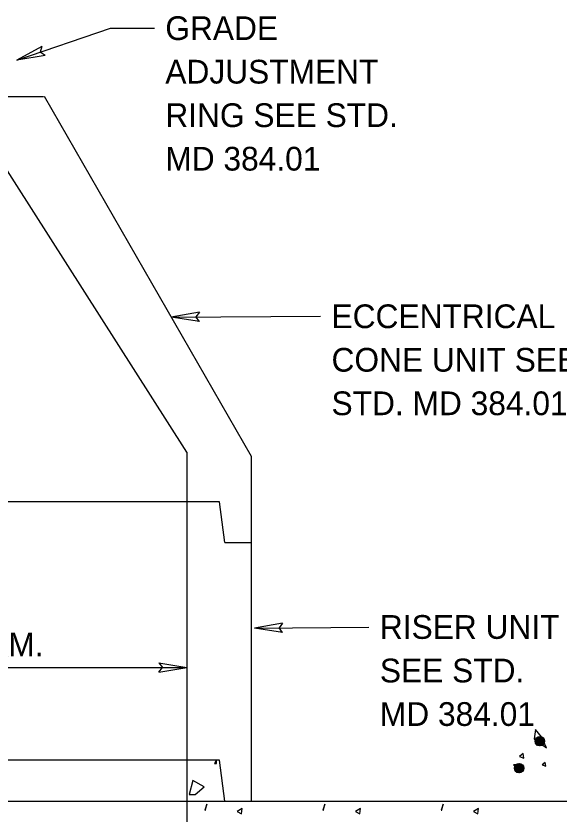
# Model space of a CAD drawing. Extents: x 8.6 to 15.9, y 6.4 to 16.6.
# Drawn here: x 10.539 to 11.914, y 12.809 to 14.827 of the extents above; entities that cross this region are included whole.
import ezdxf

# ---------------------------------------------------------------- set-up
doc = ezdxf.new("R2010")
doc.units = 0
for name, color, linetype in [('DETL-DIMS', 7, 'Continuous'), ('DETL-LINE', 7, 'Continuous'), ('DETL-NOTE', 7, 'Continuous'), ('DETL-PATT', 7, 'Continuous')]:
    doc.layers.add(name, color=color, linetype=linetype)

msp = doc.modelspace()

# ---------------------------------------------------------------- linework, layer by layer
at = {"layer": 'DETL-DIMS'}
for p, q in [((10.5416, 14.7154), (10.7783, 14.7962)), ((10.7783, 14.7962), (10.8894, 14.7962)), ((10.605, 14.7495), (10.5416, 14.7154)), ((10.605, 14.7495), (10.6005, 14.7355)), ((10.6127, 14.7271), (10.6005, 14.7355)), ((10.6127, 14.7271), (10.5416, 14.7154)), ((11.0033, 14.078), (10.9322, 14.0658)), ((10.9322, 14.0658), (11.31, 14.0678)), ((11.0034, 14.0543), (10.9322, 14.0658)), ((11.0033, 14.078), (10.9945, 14.0661)), ((11.0034, 14.0543), (10.9945, 14.0661)), ((11.2139, 13.292), (11.1429, 13.2795)), ((11.1429, 13.2795), (11.4325, 13.2822)), ((11.2141, 13.2683), (11.1429, 13.2795)), ((11.2139, 13.292), (11.2051, 13.2801)), ((11.2141, 13.2683), (11.2051, 13.2801)), ((9.6604, 13.1802), (10.972, 13.1802)), ((10.9008, 13.1918), (10.972, 13.1802)), ((10.9008, 13.1918), (10.9098, 13.18)), ((10.9009, 13.1681), (10.972, 13.1802)), ((10.9009, 13.1681), (10.9098, 13.18))]:
    msp.add_line(p, q, dxfattribs=at)
at = {"layer": 'DETL-LINE'}
for p, q in [((9.511, 14.6237), (10.609, 14.6237)), ((10.972, 13.7241), (10.3968, 14.6237)), ((10.6104, 14.6245), (11.1346, 13.7139)), ((10.972, 13.7241), (10.972, 12.6091)), ((11.1346, 13.7139), (11.1346, 12.842)), ((11.0541, 13.5991), (9.5929, 13.5991)), ((11.0675, 13.4955), (11.0541, 13.5991)), ((11.0675, 13.4955), (11.1346, 13.4955)), ((11.8622, 12.9857), (11.8534, 12.9945)), ((11.8624, 12.9861), (11.8537, 12.995)), ((11.8637, 12.998), (11.8548, 12.9893)), ((11.8638, 13.0035), (11.8549, 12.9948)), ((11.8561, 12.9859), (11.8562, 12.9984)), ((11.8649, 12.9884), (11.8562, 12.9973)), ((11.8652, 12.9888), (11.8565, 12.9977)), ((11.8665, 12.9953), (11.8575, 12.9865)), ((11.8665, 13.0007), (11.8576, 12.992)), ((11.8589, 12.9898), (11.859, 13.0023)), ((11.8677, 12.9911), (11.8589, 13)), ((11.8589, 12.9859), (11.859, 12.9984)), ((11.8676, 12.9856), (11.8589, 12.9945)), ((11.868, 12.9915), (11.8592, 13.0004)), ((11.8679, 12.986), (11.8592, 12.9949)), ((11.86, 12.9898), (11.8601, 13.0023)), ((11.86, 12.9859), (11.8601, 12.9984)), ((11.8693, 13.0035), (11.8603, 12.9947)), ((11.8692, 12.998), (11.8603, 12.9892)), ((11.8705, 12.9938), (11.8617, 13.0027)), ((11.8704, 12.9883), (11.8617, 12.9973)), ((11.8707, 12.9887), (11.8619, 12.9976)), ((11.8708, 12.9943), (11.862, 13.0031)), ((11.8627, 12.982), (11.8628, 12.9944)), ((11.8628, 12.9897), (11.8629, 13.0022)), ((11.8628, 12.9858), (11.8629, 12.9983)), ((11.8719, 12.9952), (11.863, 12.9864)), ((11.872, 13.0007), (11.8631, 12.992)), ((11.8638, 12.982), (11.8639, 12.9944)), ((11.8639, 12.9897), (11.864, 13.0022)), ((11.8639, 12.9858), (11.864, 12.9983)), ((11.8732, 12.9856), (11.8644, 12.9945)), ((11.8732, 12.991), (11.8645, 12.9999)), ((11.8735, 12.9915), (11.8647, 13.0004)), ((11.8735, 12.986), (11.8647, 12.9948)), ((11.8747, 12.9979), (11.8658, 12.9892)), ((11.8666, 12.9858), (11.8668, 12.9983)), ((11.8666, 12.9819), (11.8667, 12.9944)), ((11.8667, 12.9897), (11.8668, 13.0022)), ((11.876, 12.9938), (11.8672, 13.0027)), ((11.8762, 12.9942), (11.8675, 13.0031)), ((11.8677, 12.9819), (11.8678, 12.9944)), ((11.8678, 12.9897), (11.8679, 13.0022)), ((11.8678, 12.9858), (11.8679, 12.9983)), ((11.8705, 12.9858), (11.8706, 12.9983)), ((11.8706, 12.9897), (11.8707, 13.0021)), ((11.8716, 12.9897), (11.8718, 13.0021)), ((11.8716, 12.9858), (11.8718, 12.9983)), ((11.8649, 12.9829), (11.8561, 12.9918)), ((11.8652, 12.9833), (11.8564, 12.9922)), ((11.8692, 12.9925), (11.8603, 12.9837)), ((11.8704, 12.9828), (11.8616, 12.9917)), ((11.8707, 12.9832), (11.8619, 12.9921)), ((11.8747, 12.9924), (11.8658, 12.9837)), ((11.0541, 12.9456), (9.5929, 12.9456)), ((11.0675, 12.842), (11.0541, 12.9456)), ((11.8111, 12.9357), (11.8022, 12.927)), ((11.8062, 12.922), (11.8063, 12.9345)), ((11.8073, 12.922), (11.8075, 12.9345)), ((11.8166, 12.9357), (11.8077, 12.927)), ((11.8178, 12.926), (11.809, 12.9349)), ((11.8181, 12.9265), (11.8093, 12.9354)), ((11.8101, 12.922), (11.8102, 12.9344)), ((11.8112, 12.922), (11.8113, 12.9344)), ((11.814, 12.9219), (11.8141, 12.9344)), ((11.8233, 12.926), (11.8146, 12.9349)), ((11.8236, 12.9264), (11.8148, 12.9353)), ((11.8151, 12.9219), (11.8152, 12.9344)), ((11.8179, 12.9219), (11.818, 12.9344)), ((11.819, 12.9219), (11.8191, 12.9344)), ((11.8095, 12.9179), (11.8007, 12.9268)), ((11.8098, 12.9183), (11.801, 12.9272)), ((11.811, 12.9302), (11.8022, 12.9215)), ((11.8034, 12.9181), (11.8035, 12.9306)), ((11.8122, 12.9206), (11.8035, 12.9295)), ((11.8122, 12.9151), (11.8035, 12.924)), ((11.8125, 12.921), (11.8038, 12.9299)), ((11.8125, 12.9155), (11.8038, 12.9244)), ((11.8138, 12.933), (11.8049, 12.9242)), ((11.8138, 12.9275), (11.8049, 12.9187)), ((11.8062, 12.9181), (11.8063, 12.9306)), ((11.815, 12.9178), (11.8062, 12.9267)), ((11.815, 12.9233), (11.8063, 12.9322)), ((11.8153, 12.9182), (11.8065, 12.9271)), ((11.8153, 12.9237), (11.8066, 12.9326)), ((11.8073, 12.9181), (11.8074, 12.9306)), ((11.8166, 12.9302), (11.8076, 12.9214)), ((11.8165, 12.9247), (11.8076, 12.9159)), ((11.8178, 12.9205), (11.809, 12.9295)), ((11.8177, 12.9151), (11.809, 12.924)), ((11.818, 12.9154), (11.8092, 12.9244)), ((11.818, 12.921), (11.8093, 12.9298)), ((11.81, 12.9142), (11.8102, 12.9267)), ((11.8101, 12.9181), (11.8102, 12.9305)), ((11.8193, 12.9329), (11.8104, 12.9242)), ((11.8193, 12.9274), (11.8104, 12.9187)), ((11.8112, 12.9181), (11.8113, 12.9305)), ((11.8112, 12.9142), (11.8113, 12.9267)), ((11.8205, 12.9233), (11.8118, 12.9321)), ((11.8205, 12.9178), (11.8118, 12.9267)), ((11.8208, 12.9237), (11.812, 12.9326)), ((11.8208, 12.9182), (11.812, 12.9271)), ((11.822, 12.9247), (11.8131, 12.9159)), ((11.822, 12.9301), (11.8132, 12.9214)), ((11.8139, 12.9141), (11.814, 12.9266)), ((11.814, 12.918), (11.8141, 12.9305)), ((11.815, 12.9141), (11.8152, 12.9266)), ((11.8151, 12.918), (11.8152, 12.9305)), ((11.8179, 12.918), (11.818, 12.9305)), ((11.819, 12.918), (11.8191, 12.9305)), ((9.5795, 12.842), (11.0675, 12.842)), ((11.0675, 12.842), (11.957, 12.842))]:
    msp.add_line(p, q, dxfattribs=at)
for points in [[(11.861, 13.0008), (11.8533, 12.9932)], [(11.8582, 12.998), (11.8533, 12.9932)], [(11.8555, 12.9954), (11.8533, 12.9932)], [(11.8594, 12.9884), (11.8534, 12.9945)], [(11.8567, 12.9912), (11.8534, 12.9945)], [(11.854, 12.994), (11.8534, 12.9945)], [(11.8597, 12.9888), (11.8535, 12.9952)], [(11.857, 12.9916), (11.8535, 12.9952)], [(11.8543, 12.9944), (11.8535, 12.9952)], [(11.8609, 12.9953), (11.8542, 12.9887)], [(11.8622, 12.9911), (11.8547, 12.9988)], [(11.8595, 12.9939), (11.8547, 12.9988)], [(11.8568, 12.9967), (11.8547, 12.9988)], [(11.8625, 12.9915), (11.8549, 12.9993)], [(11.8598, 12.9943), (11.8549, 12.9993)], [(11.857, 12.9971), (11.8549, 12.9993)], [(11.855, 12.9898), (11.8551, 12.9995)], [(11.855, 12.9937), (11.8551, 12.9995)], [(11.855, 12.9873), (11.8551, 12.9984)], [(11.855, 12.9873), (11.855, 12.9945)], [(11.8551, 12.9976), (11.8551, 12.9995)], [(11.8561, 12.9898), (11.8562, 13.001)], [(11.8561, 12.9857), (11.8562, 12.9945)], [(11.8562, 12.9937), (11.8562, 13.001)], [(11.8562, 12.9976), (11.8562, 13.001)], [(11.865, 12.9939), (11.857, 13.0019)], [(11.8623, 12.9967), (11.857, 13.0019)], [(11.8595, 12.9994), (11.857, 13.0019)], [(11.8652, 12.9943), (11.8575, 13.0022)], [(11.8625, 12.9971), (11.8575, 13.0022)], [(11.8598, 12.9998), (11.8575, 13.0022)], [(11.8653, 13.005), (11.8576, 12.9975)], [(11.8588, 12.9833), (11.8589, 12.9945)], [(11.8589, 12.9937), (11.859, 13.0034)], [(11.859, 12.9975), (11.859, 13.0034)], [(11.859, 13.0014), (11.859, 13.0034)], [(11.8599, 12.9827), (11.86, 12.9945)], [(11.86, 12.9937), (11.8601, 13.004)], [(11.86, 12.9975), (11.8601, 13.004)], [(11.8601, 13.0014), (11.8601, 13.004)], [(11.8653, 13.005), (11.8604, 13.0002)], [(11.8678, 12.9966), (11.8604, 13.0041)], [(11.865, 12.9994), (11.8604, 13.0041)], [(11.8623, 13.0021), (11.8604, 13.0041)], [(11.868, 12.997), (11.8609, 13.0043)], [(11.8653, 12.9998), (11.8609, 13.0043)], [(11.8626, 13.0025), (11.8609, 13.0043)], [(11.8628, 12.9936), (11.8629, 13.0048)], [(11.8629, 12.9975), (11.8629, 13.0048)], [(11.8629, 13.0014), (11.8629, 13.0048)], [(11.8698, 13.004), (11.8631, 12.9974)], [(11.8639, 12.9936), (11.864, 13.005)], [(11.8639, 12.9975), (11.864, 13.005)], [(11.864, 13.0014), (11.864, 13.005)], [(11.8732, 12.9965), (11.8649, 13.005)], [(11.8705, 12.9993), (11.8649, 13.005)], [(11.8678, 13.0021), (11.8649, 13.005)], [(11.865, 13.0049), (11.8649, 13.005)], [(11.8735, 12.997), (11.8656, 13.005)], [(11.8708, 12.9997), (11.8656, 13.005)], [(11.8681, 13.0025), (11.8656, 13.005)], [(11.8731, 13.0018), (11.8659, 12.9947)], [(11.8667, 12.9936), (11.8668, 13.0049)], [(11.8668, 12.9975), (11.8668, 13.0049)], [(11.8668, 13.0014), (11.8668, 13.0049)], [(11.8758, 12.9884), (11.8672, 12.9972)], [(11.876, 12.989), (11.8675, 12.9976)], [(11.8678, 12.9936), (11.8679, 13.0047)], [(11.8678, 12.9975), (11.8679, 13.0047)], [(11.8679, 13.0014), (11.8679, 13.0047)], [(11.8755, 12.9987), (11.8686, 12.9919)], [(11.8767, 12.9944), (11.8686, 12.9864)], [(11.8768, 12.993), (11.8699, 12.9999)], [(11.8758, 12.9884), (11.8699, 12.9944)], [(11.8768, 12.9936), (11.8702, 13.0003)], [(11.876, 12.989), (11.8702, 12.9948)], [(11.8705, 12.9829), (11.8706, 12.9944)], [(11.8706, 12.9935), (11.8707, 13.0036)], [(11.8706, 12.9974), (11.8707, 13.0036)], [(11.8706, 13.0013), (11.8707, 13.0036)], [(11.8767, 12.9944), (11.8713, 12.9891)], [(11.8716, 12.9835), (11.8717, 12.9944)], [(11.8717, 12.9935), (11.8718, 13.0029)], [(11.8717, 12.9974), (11.8718, 13.0029)], [(11.8718, 13.0013), (11.8718, 13.0029)], [(11.8768, 12.993), (11.8727, 12.9971)], [(11.8768, 12.9936), (11.873, 12.9975)], [(11.8744, 12.9862), (11.8745, 12.9982)], [(11.8744, 12.9862), (11.8745, 12.9943)], [(11.8745, 12.9897), (11.8745, 13.0002)], [(11.8745, 12.9935), (11.8745, 13.0002)], [(11.8745, 12.9974), (11.8745, 13.0002)], [(11.8755, 12.9896), (11.8756, 12.9984)], [(11.8755, 12.988), (11.8756, 12.9982)], [(11.8755, 12.988), (11.8756, 12.9943)], [(11.8756, 12.9935), (11.8756, 12.9984)], [(11.8756, 12.9974), (11.8756, 12.9984)], [(11.8605, 12.9824), (11.8541, 12.989)], [(11.8596, 12.9833), (11.8541, 12.989)], [(11.8569, 12.9861), (11.8541, 12.989)], [(11.8542, 12.9889), (11.8541, 12.989)], [(11.8582, 12.9926), (11.8542, 12.9887)], [(11.8554, 12.9898), (11.8542, 12.9887)], [(11.8593, 12.983), (11.8547, 12.9877)], [(11.8593, 12.983), (11.8547, 12.9877)], [(11.8566, 12.9857), (11.8547, 12.9877)], [(11.855, 12.9873), (11.855, 12.9906)], [(11.8561, 12.9857), (11.8561, 12.9906)], [(11.8593, 12.983), (11.8561, 12.9863)], [(11.8637, 12.9925), (11.8564, 12.9854)], [(11.8609, 12.9898), (11.8564, 12.9854)], [(11.8581, 12.9871), (11.8564, 12.9854)], [(11.8605, 12.9824), (11.8564, 12.9867)], [(11.8588, 12.9833), (11.8589, 12.9906)], [(11.8593, 12.983), (11.8588, 12.9835)], [(11.8662, 12.9816), (11.8589, 12.989)], [(11.8605, 12.9824), (11.8591, 12.9839)], [(11.8667, 12.9817), (11.8592, 12.9894)], [(11.8664, 12.9897), (11.8595, 12.9829)], [(11.8636, 12.987), (11.8595, 12.9829)], [(11.8609, 12.9843), (11.8595, 12.9829)], [(11.8599, 12.9827), (11.86, 12.9906)], [(11.8662, 12.9816), (11.8616, 12.9862)], [(11.8667, 12.9817), (11.8619, 12.9867)], [(11.8627, 12.9818), (11.8628, 12.9905)], [(11.8719, 12.9897), (11.8637, 12.9816)], [(11.8691, 12.987), (11.8637, 12.9816)], [(11.8663, 12.9843), (11.8637, 12.9816)], [(11.8638, 12.9816), (11.8639, 12.9905)], [(11.8704, 12.9828), (11.8643, 12.989)], [(11.8708, 12.9831), (11.8646, 12.9894)], [(11.8666, 12.9817), (11.8667, 12.9905)], [(11.8736, 12.9851), (11.8671, 12.9917)], [(11.8739, 12.9855), (11.8674, 12.9921)], [(11.8677, 12.9818), (11.8678, 12.9905)], [(11.8705, 12.9829), (11.8706, 12.9905)], [(11.8754, 12.9877), (11.8705, 12.9828)], [(11.8746, 12.9869), (11.8705, 12.9828)], [(11.8718, 12.9842), (11.8705, 12.9828)], [(11.8754, 12.9877), (11.8713, 12.9836)], [(11.8716, 12.9835), (11.8717, 12.9905)], [(11.8754, 12.9877), (11.874, 12.9863)], [(11.8744, 12.9862), (11.8745, 12.9904)], [(11.8755, 12.988), (11.8756, 12.9904)], [(11.8123, 12.9261), (11.8044, 12.9341)], [(11.8096, 12.9289), (11.8044, 12.9341)], [(11.8069, 12.9317), (11.8044, 12.9341)], [(11.8126, 12.9265), (11.8048, 12.9344)], [(11.8099, 12.9293), (11.8048, 12.9344)], [(11.8071, 12.9321), (11.8048, 12.9344)], [(11.8126, 12.9373), (11.805, 12.9297)], [(11.8063, 12.9259), (11.8063, 12.9356)], [(11.8063, 12.9298), (11.8063, 12.9356)], [(11.8063, 12.9337), (11.8063, 12.9356)], [(11.8073, 12.9259), (11.8075, 12.9362)], [(11.8074, 12.9298), (11.8075, 12.9362)], [(11.8074, 12.9337), (11.8075, 12.9362)], [(11.8126, 12.9373), (11.8078, 12.9324)], [(11.8151, 12.9288), (11.8078, 12.9363)], [(11.8123, 12.9316), (11.8078, 12.9363)], [(11.8096, 12.9344), (11.8078, 12.9363)], [(11.8153, 12.9293), (11.8082, 12.9365)], [(11.8126, 12.932), (11.8082, 12.9365)], [(11.8099, 12.9348), (11.8082, 12.9365)], [(11.8102, 12.9258), (11.8102, 12.9371)], [(11.8102, 12.9297), (11.8102, 12.9371)], [(11.8102, 12.9336), (11.8102, 12.9371)], [(11.8172, 12.9362), (11.8105, 12.9297)], [(11.8112, 12.9258), (11.8113, 12.9372)], [(11.8113, 12.9297), (11.8113, 12.9372)], [(11.8113, 12.9336), (11.8113, 12.9372)], [(11.8206, 12.9288), (11.8123, 12.9373)], [(11.8179, 12.9315), (11.8123, 12.9373)], [(11.8151, 12.9343), (11.8123, 12.9373)], [(11.8124, 12.9371), (11.8123, 12.9373)], [(11.8209, 12.9292), (11.8129, 12.9373)], [(11.8181, 12.932), (11.8129, 12.9373)], [(11.8154, 12.9347), (11.8129, 12.9373)], [(11.8205, 12.934), (11.8132, 12.9269)], [(11.814, 12.9258), (11.8141, 12.9371)], [(11.8141, 12.9297), (11.8141, 12.9371)], [(11.8141, 12.9336), (11.8141, 12.9371)], [(11.8151, 12.9258), (11.8152, 12.9369)], [(11.8152, 12.9297), (11.8152, 12.9369)], [(11.8152, 12.9336), (11.8152, 12.9369)], [(11.8179, 12.9258), (11.818, 12.9358)], [(11.818, 12.9297), (11.818, 12.9358)], [(11.818, 12.9335), (11.818, 12.9358)], [(11.819, 12.9258), (11.8191, 12.9351)], [(11.819, 12.9297), (11.8191, 12.9351)], [(11.8191, 12.9335), (11.8191, 12.9351)], [(11.8083, 12.933), (11.8006, 12.9254)], [(11.8056, 12.9303), (11.8006, 12.9254)], [(11.8028, 12.9276), (11.8006, 12.9254)], [(11.8068, 12.9206), (11.8007, 12.9268)], [(11.804, 12.9234), (11.8007, 12.9268)], [(11.8013, 12.9262), (11.8007, 12.9268)], [(11.807, 12.9211), (11.8008, 12.9274)], [(11.8043, 12.9238), (11.8008, 12.9274)], [(11.8016, 12.9266), (11.8008, 12.9274)], [(11.8079, 12.9147), (11.8015, 12.9212)], [(11.807, 12.9155), (11.8015, 12.9212)], [(11.8042, 12.9183), (11.8015, 12.9212)], [(11.8016, 12.9211), (11.8015, 12.9212)], [(11.8083, 12.9275), (11.8016, 12.9209)], [(11.8055, 12.9248), (11.8016, 12.9209)], [(11.8027, 12.9221), (11.8016, 12.9209)], [(11.8095, 12.9234), (11.802, 12.931)], [(11.8068, 12.9261), (11.802, 12.931)], [(11.8041, 12.9289), (11.802, 12.931)], [(11.8066, 12.9153), (11.802, 12.9199)], [(11.8066, 12.9153), (11.802, 12.9199)], [(11.804, 12.918), (11.802, 12.9199)], [(11.8023, 12.922), (11.8024, 12.9317)], [(11.8098, 12.9238), (11.8023, 12.9315)], [(11.8071, 12.9265), (11.8023, 12.9315)], [(11.8043, 12.9293), (11.8023, 12.9315)], [(11.8023, 12.9195), (11.8024, 12.9306)], [(11.8023, 12.9195), (11.8024, 12.9267)], [(11.8023, 12.9195), (11.8023, 12.9228)], [(11.8024, 12.9259), (11.8024, 12.9317)], [(11.8024, 12.9298), (11.8024, 12.9317)], [(11.8034, 12.918), (11.8035, 12.9267)], [(11.8034, 12.918), (11.8035, 12.9228)], [(11.8066, 12.9153), (11.8034, 12.9185)], [(11.8035, 12.922), (11.8035, 12.9333)], [(11.8035, 12.9259), (11.8035, 12.9333)], [(11.8035, 12.9298), (11.8035, 12.9333)], [(11.811, 12.9247), (11.8037, 12.9176)], [(11.8082, 12.922), (11.8037, 12.9176)], [(11.8055, 12.9193), (11.8037, 12.9176)], [(11.8079, 12.9147), (11.8037, 12.9189)], [(11.8066, 12.9153), (11.8061, 12.9157)], [(11.8062, 12.9155), (11.8063, 12.9267)], [(11.8062, 12.9155), (11.8062, 12.9228)], [(11.8135, 12.9138), (11.8062, 12.9212)], [(11.8079, 12.9147), (11.8064, 12.9161)], [(11.814, 12.9139), (11.8065, 12.9217)], [(11.8138, 12.922), (11.8068, 12.9151)], [(11.811, 12.9193), (11.8068, 12.9151)], [(11.8082, 12.9165), (11.8068, 12.9151)], [(11.8073, 12.9149), (11.8074, 12.9267)], [(11.8073, 12.9149), (11.8073, 12.9228)], [(11.8135, 12.9138), (11.8089, 12.9184)], [(11.814, 12.9139), (11.8092, 12.9189)], [(11.81, 12.914), (11.8101, 12.9228)], [(11.8192, 12.9219), (11.811, 12.9138)], [(11.8165, 12.9192), (11.811, 12.9138)], [(11.8137, 12.9165), (11.811, 12.9138)], [(11.8112, 12.9138), (11.8112, 12.9228)], [(11.8178, 12.915), (11.8117, 12.9212)], [(11.8182, 12.9153), (11.812, 12.9216)], [(11.8139, 12.9139), (11.814, 12.9227)], [(11.8231, 12.9207), (11.8145, 12.9294)], [(11.8209, 12.9174), (11.8145, 12.9239)], [(11.8233, 12.9212), (11.8148, 12.9298)], [(11.8212, 12.9178), (11.8148, 12.9243)], [(11.815, 12.9141), (11.8151, 12.9227)], [(11.8228, 12.9309), (11.8159, 12.9241)], [(11.824, 12.9267), (11.8159, 12.9186)], [(11.8231, 12.9207), (11.8172, 12.9266)], [(11.8241, 12.9252), (11.8173, 12.9321)], [(11.8233, 12.9212), (11.8175, 12.927)], [(11.8241, 12.9258), (11.8176, 12.9325)], [(11.8178, 12.9151), (11.8179, 12.9266)], [(11.8178, 12.9151), (11.8179, 12.9227)], [(11.8227, 12.9199), (11.8178, 12.9151)], [(11.8219, 12.9191), (11.8178, 12.9151)], [(11.8192, 12.9164), (11.8178, 12.9151)], [(11.8227, 12.9199), (11.8186, 12.9158)], [(11.824, 12.9267), (11.8187, 12.9213)], [(11.8189, 12.9158), (11.819, 12.9266)], [(11.8189, 12.9158), (11.819, 12.9227)], [(11.8241, 12.9252), (11.82, 12.9294)], [(11.8241, 12.9258), (11.8203, 12.9297)], [(11.8227, 12.9199), (11.8214, 12.9185)], [(11.8218, 12.9219), (11.8219, 12.9324)], [(11.8218, 12.9258), (11.8219, 12.9324)], [(11.8218, 12.9184), (11.8219, 12.9304)], [(11.8218, 12.9184), (11.8218, 12.9265)], [(11.8218, 12.9184), (11.8218, 12.9227)], [(11.8219, 12.9297), (11.8219, 12.9324)], [(11.8229, 12.9218), (11.823, 12.9306)], [(11.8229, 12.9257), (11.823, 12.9306)], [(11.8229, 12.9296), (11.823, 12.9306)], [(11.8229, 12.9202), (11.8229, 12.9304)], [(11.8229, 12.9202), (11.8229, 12.9265)], [(11.8229, 12.9202), (11.8229, 12.9227)]]:
    msp.add_lwpolyline(points, dxfattribs=at)
for centre in [(11.8651, 12.9933), (11.8124, 12.9255)]:
    msp.add_circle(centre, 0.0118, dxfattribs=at)
at = {"layer": 'DETL-PATT'}
for points in [[(11.8542, 13.0234), (11.8507, 12.9994), (11.8822, 12.9768), (11.8693, 13.0048)], [(11.8227, 12.9621), (11.8133, 12.9545), (11.8245, 12.9505)], [(11.7982, 12.9341), (11.804, 12.9283), (11.8076, 12.9341)], [(11.8711, 12.9341), (11.8805, 12.9301), (11.8787, 12.9394)], [(10.9925, 12.8587), (11.0151, 12.8778), (10.9871, 12.8943), (10.9778, 12.8587)], [(11.0169, 12.8196), (11.0187, 12.8196), (11.0222, 12.8347)], [(11.316, 12.8196), (11.3178, 12.8196), (11.3213, 12.8347)], [(11.6151, 12.8196), (11.6169, 12.8196), (11.6205, 12.8347)], [(11.0991, 12.8161), (11.1102, 12.8103), (11.112, 12.8236)], [(11.3982, 12.8161), (11.4093, 12.8103), (11.4111, 12.8236)], [(11.6973, 12.8161), (11.7085, 12.8103), (11.7102, 12.8236)]]:
    msp.add_lwpolyline(points, close=True, dxfattribs=at)
msp.add_lwpolyline([(11.046, 12.9456), (11.0413, 12.9374), (11.0467, 12.9374), (11.0467, 12.9456)], dxfattribs=at)

# ---------------------------------------------------------------- texts
at = {"layer": 'DETL-NOTE'}
for s, p in [('GRADE', (10.9172, 14.7662)), ('ADJUSTMENT', (10.9172, 14.6562)), ('RING SEE STD.', (10.9172, 14.5462)), ('MD 384.01', (10.9172, 14.4362)), ('ECCENTRICAL', (11.3378, 14.0378)), ('CONE UNIT SEE', (11.3378, 13.9278)), ('STD. MD 384.01', (11.3378, 13.8178)), ('RISER UNIT', (11.4602, 13.2523)), ('DIAM.', (10.3861, 13.208)), ('SEE STD.', (11.4602, 13.1422)), ('MD 384.01', (11.4602, 13.0322))]:
    msp.add_text(s, height=0.06, dxfattribs=at).set_placement(p)

doc.saveas('drawing.dxf')
